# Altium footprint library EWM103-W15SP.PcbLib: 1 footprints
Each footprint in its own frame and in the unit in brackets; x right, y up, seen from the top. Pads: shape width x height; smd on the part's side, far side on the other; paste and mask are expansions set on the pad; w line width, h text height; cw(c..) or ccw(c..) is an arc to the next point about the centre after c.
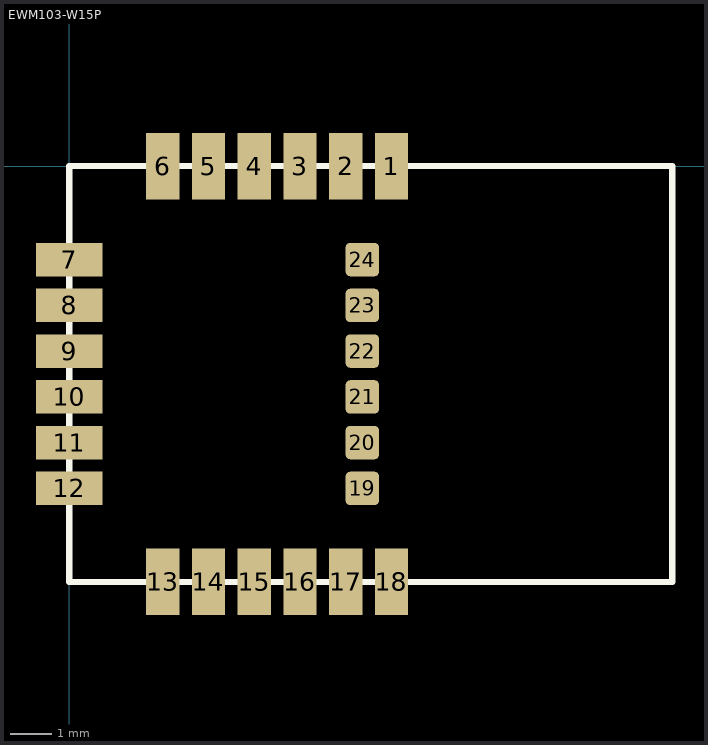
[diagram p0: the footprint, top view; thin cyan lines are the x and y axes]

## EWM103-W15P [mm]
pads (24):
  rect 0.8x1.6 smd mask+0: 1(7.75,0) 2(6.65,0) 3(5.55,0) 4(4.45,0) 5(3.35,0) 6(2.25,0) 13(2.25,-10) 14(3.35,-10) 15(4.45,-10) 16(5.55,-10) 17(6.65,-10) 18(7.75,-10)
  rect 1.6x0.8 smd mask+0: 7(0,-2.25) 8(0,-3.35) 9(0,-4.45) 10(0,-5.55) 11(0,-6.65) 12(0,-7.75)
  rrect25% 0.8x0.8 smd mask+0: 19(7.05,-7.75) 20(7.05,-6.65) 21(7.05,-5.55) 22(7.05,-4.45) 23(7.05,-3.35) 24(7.05,-2.25)
Top Overlay:
  lines w0.152: 0,-10 14.5,-10 14.5,0 0,0 0,-10
Mechanical 10:
  text "'.Designator'" at -0.33,-16.817 h1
